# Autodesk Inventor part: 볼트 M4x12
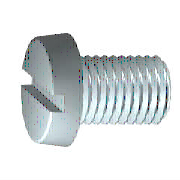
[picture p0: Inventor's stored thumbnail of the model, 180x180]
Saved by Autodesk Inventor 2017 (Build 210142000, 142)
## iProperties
Created: 2012-02
Part Number: 볼트 M4x12
Material: 강철, 연강
Description: 6각머리 태핑 나사
Document SubType Name: Modeling
Standard: KS B 1021
Designer: mduedu
Standards Organization: KS
Language: ko-KR
Size Designation: A  M 4 x 12
Categories: <MemberInstance><Categories><Category DisplayName="조임쇠" InternalName="e4da775c-781d-43d5-af7c-5136215cf5a6" Mnemonic="FSTN"><Category DisplayName="볼트" InternalN
Density: 1 g/cm^3
Appearance: 강철
IsCustomPart: 0
Author: mduedu
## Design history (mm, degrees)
body "Solid1"
revolve "본체" stored, may be unused: angle "d8" = 90 deg
sketch "스케치2"
  geometry: L1 (0, 0)-(0, 3.273) reference; L2 (-3.5, 0.6)-(3.5, 0.6); L3 (3.5, 0.6)-(3.5, -0.6); L4 (3.5, -0.6)-(-3.5, -0.6); L5 (-3.5, -0.6)-(-3.5, 0.6); L6 (-3.5, 0)-(3.5, 0); L7 (0, 0.6)-(0, -0.6); C1 r 3.5 at (0, 0) reference; 1 further point
  constraints: 12 end point, 5 midpoint, 2 parallel, 1 collinear, 1 horizontal, 1 perpendicular
  dimensions: "d11" = 1.2 distance of L4.end L2.start (= SBR); "d12" = 7 distance of L2.start L2.end (= KOD)
fillet "모깎기1" dims "d14" = 0.2 (= RR)
extrude "슬롯" cut sketch "스케치2" distance "d19" = 1.1 (= STI); taper "d20" = 0 deg
feature "스레드" dims "d15" = 10.6 (= GEL), "d16" = 0
chamfer "모따기1" distance "d17" = 0.42941 (= -0.5 x SPD + 0.5 x GD); stored, may be unused: second distance "d18" = 0.42952 (computed from GUL), angle "d36" = 45 deg
workplane "Work Plane1"
sketch "스케치1"
  geometry: L1 (-2.6, 0)-(12, 0); L2 (12, 0)-(12, 2); L3 (12, 2)-(1.4, 2); L4 (1.4, 2)-(0.97, 1.785); L5 (0.97, 1.785)-(0, 1.785); L6 (0, 1.785)-(0, 3.5); L7 (-5.52, 0)-(14.92, 0) reference; L8 (0, -0.7)-(0, 4.2) reference; L9 (-2.6, 0)-(-2.6, 3.273); L10 (0, 3.5)-(-2.6, 3.273); L11 (1.4, 2)-(0, 2)
  constraints: 18 end point, 4 parallel, 2 collinear, 2 perpendicular, 1 horizontal, 1 point on line
  dimensions: "d0" = 12 distance between parallel lines of L2 L6 (= NLG); "d1" = 10.6 distance from line of L3.end L2 (= GEL); "d2" = 0.42952 horizontal distance of L4.end L3.end (computed from GAL); "d3" = 2.6 distance from line of L1.start L6 (= KOH); "d4" = 4 diameter of L3 L1 (= GD); "d5" = 3.5705 diameter of L5 L1 (= BDM); "d9" = 7 diameter of L6.end L1 (= KOD); "d10" = 5 deg angle of L10 L1 (= KEWI)
other parameters: "GD" = 4 (= NND) [user parameter; used in 2 equation terms], "NLG" = 12 [user parameter; used in 1 equation term], "GEL" = 10.6 [user parameter; used in 2 equation terms], "KOD" = 7 [user parameter; used in 2 equation terms], "KOH" = 2.6 [user parameter; used in 1 equation term], "GAL" = 0.42941 (= 0.61345 x PTC) [user parameter; used in 1 equation term], "SPD" = 3.14117 (= NND - 1.2269 x PTC) [user parameter; used in 1 equation term], "BDM" = 3.5705 [user parameter; used in 1 equation term], "GUL" = 0.42941 (= 0.61345 x PTC) [user parameter; used in 1 equation term], "RR" = 0.2 [user parameter; used in 1 equation term], "d7" = 0, "SBR" = 1.2 [user parameter; used in 1 equation term], "STI" = 1.1 [user parameter; used in 1 equation term], "KEWI" = 5 deg [user parameter; used in 1 equation term], "d37" = 0, "d39" = 0, "PTC" = 0.7 [user parameter; used in 5 equation terms], "THREADDIA" = 4 [user parameter; used in 1 equation term], "TOA" = 30 deg [user parameter], "TPU" = 14.28571 (computed from PTC) [user parameter], "NND" = 4 [user parameter; used in 2 equation terms], "GD1" = 3.14117 (= THREADDIA - 1.2269 x PTC) [user parameter]
